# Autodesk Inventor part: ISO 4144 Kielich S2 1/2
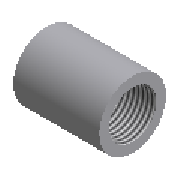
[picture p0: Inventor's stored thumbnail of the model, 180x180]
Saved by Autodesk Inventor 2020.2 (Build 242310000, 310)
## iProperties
Manager: www.cadconsulting.pl
Company: Fabian Stasiak CAD Consulting
NAME: PIPING: ISO 4144 Socket M2
DATA: <meta><inlinegroups number="1" deflen="3.4"></inlinegroups><connections number="2"></connections><angles><a>3.14159265358979</a></angles></meta>
IsCustomPart: 0
Created: 2014-02
Part Number: ISO 4144 Kielich S2 1/2
Material: Stal nierdzewna
Description: Rurociągi - Elementy ze stali nierdzewnej gwintowane zgodnie z ISO 7-1 - Kielich S2
Document SubType Name: Modeling
Standard: ISO 4144
Designer: F.Stasiak
Standard Revision: Second edition 2003-03-15
Standards Organization: ISO
Language: pl-PL
Size Designation: 1/2
Categories: <MemberInstance><Categories><Category DisplayName="Rury cienko- i grubościenne" InternalName="4347fa0f-2144-441d-94cd-e3e15c92b736" Mnemonic="TUBEANDPIPE"><Cate
Density: 1 g/cm^3
Appearance: Częściowo polerowana
Catalog Web Link: www.expertbooks.pl
Author: F.Stasiak
Subject: Zbiór ćwiczeń. Autodesk Inventor 2020. Kurs Professional
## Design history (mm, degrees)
sketch "Sketch1"
  geometry: L1 (34, 9.316)-(34, 13.2); L2 (34, 13.2)-(0, 13.2); L3 (34, 9.316)-(34, 0); L4 (0, 0)-(34, 0); L5 (17, 0)-(17, 13.2); L6 (0, 9.315)-(0, 13.2); L7 (0, 9.315)-(0, 0); L8 (0, -2.64)-(0, 15.84) reference; L9 (-6.8, 0)-(40.8, 0) reference; L10 (0, 9.315)-(34, 9.316)
  constraints: 16 end point, 2 collinear, 2 midpoint, 2 parallel, 1 perpendicular, 1 symmetric about line, 2 other
  dimensions: "d0" = 26.4 diameter of L2.end L4 (= d); "d1" = 18.631 diameter of L1.start L4 (= MD); "d2" = 34 distance of L2.end L1.end (= L)
revolve "Revolution1" sketch "Sketch1" stored, may be unused: angle "d12" = 90 deg
workpoint "Work Point1"
workpoint "Work Point2"
workaxis "Work Axis1"
workpoint "Work Point3"
workaxis "Work Axis2"
workpoint "Work Point4"
workaxis "Work Axis3"
workaxis "Work Axis4"
body "Solid1"
feature "Gwint1" dims "d13" = 25.4, "d14" = 0
other parameters: "d" = 26.4 [user parameter; used in 1 equation term], "MD" = 18.631 [user parameter; used in 1 equation term], "L" = 34 [user parameter; used in 1 equation term], "Size_Designation" = 5 [user parameter]
